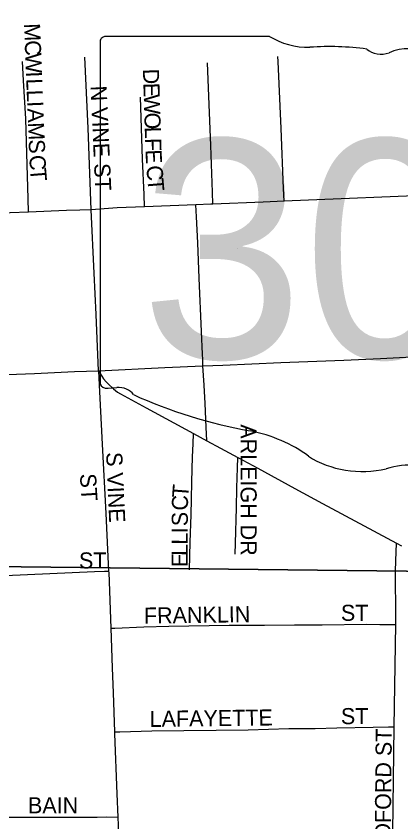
# Model space of a CAD drawing. Extents: x -9.1 to 34, y -3.1 to 22.
# Drawn here: x 5.5372 to 5.7636, y 19.6185 to 20.0929 of the extents above; entities that cross this region are included whole.
import ezdxf

# ---------------------------------------------------------------- set-up
doc = ezdxf.new("R2010")
doc.units = 0
for name, color, linetype in [('GM_X_City_Street', 7, 'Continuous'), ('GM_X_City_Street_Text', 7, 'Continuous'), ('GM_X_Section', 7, 'Continuous'), ('GM_X_State_Location', 7, 'Continuous'), ('GM_X_State_Route', 7, 'Continuous'), ('GM_X_State_Shield', 7, 'Continuous')]:
    doc.layers.add(name, color=color, linetype=linetype)

msp = doc.modelspace()

# ---------------------------------------------------------------- linework, layer by layer
at = {"layer": 'GM_X_City_Street'}
for points in [[(5.58144, 19.97895), (5.57966, 20.02685), (5.57762, 20.06874)], [(5.69494, 19.98395), (5.69462, 19.99142), (5.69311, 20.02677), (5.69145, 20.06616), (5.69128, 20.06919)], [(5.54439, 19.97757), (5.54418, 19.98562), (5.54368, 20.00539), (5.54281, 20.03252), (5.54162, 20.05505), (5.54103, 20.06618)], [(5.65306, 19.98223), (5.65279, 19.98932), (5.65176, 20.01682), (5.65085, 20.04085), (5.64992, 20.06539)], [(5.61283, 19.98062), (5.6125, 19.98779), (5.61155, 20.00868), (5.61036, 20.0451)], [(5.64715, 19.88695), (5.64698, 19.89073), (5.64685, 19.89386), (5.64629, 19.90719), (5.64496, 19.93866), (5.64409, 19.95933), (5.64336, 19.97468), (5.64301, 19.98183)], [(5.58561, 19.88409), (5.58635, 19.87178), (5.5879, 19.8409), (5.59002, 19.80011), (5.59162, 19.76618)], [(5.64943, 19.84283), (5.64906, 19.85097), (5.64841, 19.86491), (5.6478, 19.87556), (5.64715, 19.88695)], [(5.63924, 19.7669), (5.63968, 19.7832), (5.64012, 19.79935), (5.64032, 19.80841), (5.64055, 19.81878), (5.64098, 19.83341), (5.64129, 19.84109), (5.64153, 19.84712)], [(5.66608, 19.77619), (5.6663, 19.78252), (5.66686, 19.80343), (5.66717, 19.81516), (5.66748, 19.82693), (5.66764, 19.83305)], [(5.76061, 19.73473), (5.76067, 19.74151), (5.76056, 19.76315), (5.76051, 19.76605), (5.76071, 19.7721), (5.76107, 19.78269)], [(5.51812, 19.76306), (5.53065, 19.76359), (5.58323, 19.76587), (5.58912, 19.76609), (5.59162, 19.76618)], [(5.59162, 19.76618), (5.59166, 19.76531), (5.59291, 19.73248)], [(5.59291, 19.73248), (5.59535, 19.7326), (5.61233, 19.7334), (5.62712, 19.7338), (5.66248, 19.73441), (5.68337, 19.73431), (5.70094, 19.73442), (5.71739, 19.73454), (5.74341, 19.73483), (5.75134, 19.73474), (5.75849, 19.73474), (5.76061, 19.73473)], [(5.59291, 19.73248), (5.59379, 19.70923), (5.5943, 19.69457), (5.5951, 19.67154)], [(5.75975, 19.67446), (5.76061, 19.73473)], [(5.5951, 19.67154), (5.59823, 19.67161), (5.6171, 19.67206), (5.67368, 19.67274), (5.69768, 19.67341), (5.71322, 19.67354), (5.72599, 19.67381), (5.7473, 19.67425), (5.7564, 19.6744), (5.75975, 19.67446)], [(5.75842, 19.58129), (5.75975, 19.67446)], [(5.5951, 19.67154), (5.59514, 19.67037), (5.59654, 19.63494), (5.59708, 19.6213)], [(5.5241, 19.62132), (5.53913, 19.62127), (5.56737, 19.62118), (5.58496, 19.62132), (5.59053, 19.62138), (5.59708, 19.6213)], [(5.59708, 19.6213), (5.59857, 19.58369)]]:
    msp.add_lwpolyline(points, dxfattribs=at)
at = {"layer": 'GM_X_Section'}
for points in [[(5.2279, 20.77322), (6.2403, 20.76479), (6.2379, 19.76083), (5.226, 19.77229)], [(5.226, 19.77229), (6.2379, 19.76083), (6.22532, 18.76489), (5.22068, 18.771)]]:
    msp.add_lwpolyline(points, close=True, dxfattribs=at)
at = {"layer": 'GM_X_State_Route'}
for points in [[(5.91225, 19.9936), (5.90856, 19.99434), (5.9052, 19.99477), (5.90255, 19.99501), (5.89978, 19.99507), (5.89387, 19.99473), (5.89074, 19.99418), (5.8862, 19.99339), (5.8828, 19.99242), (5.88054, 19.99211), (5.87723, 19.99203), (5.87324, 19.9918), (5.8496, 19.99044), (5.82114, 19.98922), (5.80489, 19.98853), (5.79087, 19.98793), (5.69494, 19.98395), (5.68265, 19.98344), (5.65306, 19.98223), (5.65185, 19.98218), (5.64301, 19.98183)], [(5.58144, 19.97895), (5.57461, 19.9787), (5.56693, 19.97843), (5.54439, 19.97757), (5.53371, 19.97716), (5.50956, 19.97596), (5.49713, 19.97535), (5.45737, 19.97384), (5.43498, 19.97251)], [(5.64301, 19.98183), (5.61283, 19.98062), (5.5966, 19.97997), (5.58144, 19.97895)], [(5.58561, 19.88409), (5.58436, 19.91718), (5.5831, 19.94148), (5.58144, 19.97895)], [(5.58561, 19.88409), (5.62476, 19.88609), (5.64715, 19.88695), (5.65883, 19.88739), (5.69289, 19.88906), (5.73009, 19.89026), (5.75173, 19.89132), (5.77029, 19.89227), (5.81369, 19.89373), (5.82078, 19.89404), (5.86634, 19.89624), (5.88233, 19.89683), (5.89849, 19.89747)], [(5.43845, 19.87782), (5.44879, 19.87814), (5.48925, 19.88022), (5.51415, 19.88125), (5.52659, 19.88176), (5.54796, 19.88257), (5.57164, 19.88358), (5.58561, 19.88409)], [(5.58561, 19.88409), (5.58861, 19.87933), (5.59015, 19.87753), (5.59149, 19.87613), (5.59444, 19.87338), (5.59683, 19.87157), (5.59855, 19.87058), (5.61375, 19.86223), (5.64153, 19.84712), (5.64943, 19.84283), (5.65747, 19.83845), (5.66764, 19.83305), (5.67945, 19.82677), (5.70129, 19.81487), (5.71758, 19.806), (5.76107, 19.78269), (5.764, 19.78112)]]:
    msp.add_lwpolyline(points, dxfattribs=at)
at = {"layer": 'GM_X_State_Shield'}
for p, q in [((5.58661, 20.07752), (5.58661, 19.8774)), ((5.68638, 20.08096), (5.58986, 20.08096))]:
    msp.add_line(p, q, dxfattribs=at)
for centre, major_axis, start_param, end_param in [((5.59039, 20.07794), (0.00382, 0), 1.712693, 3.28349), ((5.70937, 20.10419), (0.03703, 0), 4.042523, 4.731795), ((5.72164, 19.96861), (0.13295, 0), 1.404758, 1.657858), ((5.75183, 20.07898), (0.01068, 0), 3.836095, 5.185415), ((5.76751, 20.05585), (0.02221, 0), 0.950623, 2.079405), ((5.59042, 19.87696), (0.00385, 0), 3.00124, 4.508301), ((5.59101, 19.89743), (0.0294, 0), 4.665946, 4.897461), ((5.59702, 19.86585), (0.0106, 0), 0.519207, 1.627899), ((5.73085, 20.04565), (0.2524, 0), 4.195997, 4.488961), ((5.6556, 19.78749), (0.07897, 0), 0.823519, 1.323587), ((5.74101, 19.86486), (0.05011, 0), 4.026481, 4.996735), ((5.76997, 19.79567), (0.04118, 0), 1.495662, 1.94098)]:
    msp.add_ellipse(centre, major_axis=major_axis, ratio=0.8, start_param=start_param, end_param=end_param, dxfattribs=at)

# ---------------------------------------------------------------- texts
at = {"layer": 'GM_X_City_Street_Text'}
for s, height, rotation, p in [('M', 0.00947, 272.2957, (5.54179, 20.08849)), ('C', 0.00947, 272.2975, (5.54219, 20.0785)), ('W', 0.00947, 272.2873, (5.54249, 20.07101)), ('I', 0.00947, 272.3089, (5.54293, 20.06018)), ('D', 0.00947, 271.7926, (5.61179, 20.06181)), ('L', 0.00947, 272.2961, (5.54309, 20.05602)), ('L', 0.00947, 272.2903, (5.54336, 20.04936)), ('N VINE ST', 0.00947, 272.6024, (5.58096, 20.05178)), ('E', 0.00947, 271.8022, (5.61205, 20.05348)), ('W', 0.00947, 271.8088, (5.61226, 20.04681)), ('I', 0.00947, 272.2912, (5.54363, 20.0427)), ('A', 0.00947, 272.2923, (5.5438, 20.03854)), ('O', 0.00947, 271.7926, (5.6126, 20.03599)), ('M', 0.00947, 272.2937, (5.54413, 20.03021)), ('L', 0.00947, 271.7891, (5.61286, 20.02766)), ('F', 0.00947, 271.7891, (5.61307, 20.021)), ('S', 0.00947, 272.2903, (5.54453, 20.02022)), ('C', 0.00947, 273.0577, (5.54491, 20.01092)), ('E', 0.00947, 272.6285, (5.61329, 20.01418)), ('T', 0.00947, 274.4938, (5.54532, 20.00317)), ('C', 0.00947, 274.6379, (5.61379, 20.00467)), ('T', 0.00947, 274.7691, (5.6144, 19.99717)), ('ARLEIGH DR', 0.00947, 270, (5.66929, 19.85259)), ('S VINE', 0.00947, 272.6012, (5.59012, 19.836)), ('ST', 0.00947, 273.5746, (5.5747, 19.82335)), ('T', 0.00947, 85.7061, (5.63839, 19.80907)), ('C', 0.00947, 88.8829, (5.63825, 19.80171)), ('S', 0.00947, 89.9707, (5.63824, 19.79259)), ('I', 0.00947, 89.9563, (5.63824, 19.78842)), ('L', 0.00947, 89.9707, (5.63824, 19.78175)), ('L', 0.00947, 89.9453, (5.63823, 19.77508)), ('ST', 0.00947, 0, (5.57418, 19.7677)), ('E', 0.00947, 89.9727, (5.63823, 19.76842)), ('FRANKLIN', 0.00947, 0.8201, (5.61247, 19.7352)), ('ST', 0.00947, 0, (5.72834, 19.73687)), ('LAFAYETTE', 0.00947, 0.7158, (5.61582, 19.67437)), ('ST', 0.00947, 0, (5.72834, 19.67604)), ('BRADFORD ST', 0.0094697, 89.3972, (5.7574, 19.58261)), ('BAIN', 0.00947, 0, (5.54418, 19.62354))]:
    msp.add_text(s, height=height, rotation=rotation, dxfattribs=at).set_placement(p)
at = {"layer": 'GM_X_State_Location'}
for s in ['s', 'r']:
    msp.add_text(s, height=0.000189, dxfattribs=at).set_placement((5.7477, 19.96415))
msp.add_text('309D', height=0.000189, rotation=0, dxfattribs=at).set_placement((5.66751, 19.95583))
at = {"layer": 'GM_X_State_Shield'}
msp.add_text('309D', height=0.128788, dxfattribs=at).set_placement((5.61048, 19.89151))

doc.saveas('drawing.dxf')
